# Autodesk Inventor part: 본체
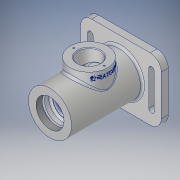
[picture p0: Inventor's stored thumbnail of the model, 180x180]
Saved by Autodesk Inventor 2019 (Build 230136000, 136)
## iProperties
Created: 2021-07
Part Number: 본체
Material: 알루미늄 6061
Document SubType Name: Modeling
Designer: jun-2-10
Mass: 738.051 g
Surface Area: 647.155 cm^2
Volume: 273.352 cm^3
Density: 2.7 g/cm^3
Appearance: 알루미늄 - 평지
Author: jun-2-10
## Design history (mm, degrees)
sketch "스케치1"
  geometry: C1 r 31 at (0, 0); 1 further point
  constraints: 1 centre point, 1 coincident
  dimensions: "d0" = 62 diameter of C1
extrude "돌출1" new body sketch "스케치1" stored distance "d1" = 115; taper "d2" = 0 deg
sketch "스케치2"
  geometry: C1 r 35 at (0, 0); 1 further point
  constraints: 1 centre point, 1 coincident
  dimensions: "d3" = 70 diameter of C1
extrude "돌출2" join sketch "스케치2" distance "d4" = 3; taper "d5" = 0 deg
sketch "스케치3"
  geometry: L1 (-58, 45)-(58, 45); L2 (58, 45)-(58, -45); L3 (58, -45)-(-58, -45); L4 (-58, -45)-(-58, 45); L5 (-58, 45)-(58, -45); L6 (58, 45)-(-58, -45); 1 further point
  constraints: 12 end point, 2 midpoint, 2 parallel, 1 horizontal, 1 perpendicular
  dimensions: "d6" = 116 distance of L1.start L1.end; "d7" = 90 distance of L1.end L2.end
extrude "돌출3" join sketch "스케치3" distance "d8" = 10; taper "d9" = 0 deg
sketch "스케치4"
  geometry: L1 (17.5, 31.5)-(17.5, 20.5); L2 (17.5, 20.5)-(23, 20.5); L3 (26, 17.5)-(26, -14.5); L4 (23, -17.5)-(17.5, -17.5); L5 (17.5, -17.5)-(17.5, -28.5); L6 (17.5, -28.5)-(16, -28.5); L7 (16, -28.5)-(16, -30.5); L8 (13, -33.5)-(10, -33.5); L9 (10, -33.5)-(10, -36.2); L10 (16.779, -45.318)-(22, -57.5); L11 (0, 80.5)-(0, -80.5) reference; L12 (31, -44.5)-(31, 57.5) reference; L13 (-31, -44.5)-(-31, 57.5) reference; L14 (35, -57.5)-(-35, -57.5) reference; L15 (14.022, -43.5)-(12.5, -43.5); L16 (12.5, -43.5)-(12.5, -36.5); L17 (12.2, -36.2)-(10, -36.2); L18 (17.5, 31.5)-(18.5, 31.5); L19 (18.5, 31.5)-(18.5, 33.25); L20 (18.5, 33.25)-(17.5, 33.25); L21 (17.5, 33.25)-(17.5, 36.5); L22 (17.5, 36.5)-(17, 36.5); L23 (20, 39.5)-(20, 45.5); L24 (20, 45.5)-(24, 45.5); L25 (24, 45.5)-(24, 48.5); L26 (24, 48.5)-(21, 48.5); L27 (31, 57.5)-(-31, 57.5) reference; L28 (22, -57.5)-(0, -57.5); L29 (21, 48.5)-(0, 48.5); L30 (0, 48.5)-(0, -57.5); A1 r 3 centre (17, 39.5) between (17, 36.5) and (20, 39.5); A2 r 3 centre (13, -30.5) between (13, -33.5) and (16, -30.5); A3 r 0.3 centre (12.2, -36.5) between (12.5, -36.5) and (12.2, -36.2); A4 r 3 centre (23, 17.5) between (26, 17.5) and (23, 20.5); A5 r 3 centre (23, -14.5) between (23, -17.5) and (26, -14.5); A6 r 3 centre (14.022, -46.5) between (16.779, -45.318) and (14.022, -43.5); 7 further points
  constraints: 50 end point, 20 perpendicular, 12 point on circle, 12 tangent, 10 point on line, 6 centre point, 2 horizontal, 1 equal radius, 1 midpoint
  dimensions: "d11" = 14 vertical distance of L10.end point (16, -43.5); "d12" = 44 diameter of L10.end L11; "d13" = 32 diameter of point (16, -43.5) L11; "d14" = 24 distance between parallel lines of L14 L8; "d15" = 20 diameter of L9 L11; "d16" = 52 diameter of L3 L11; "d17" = 35 diameter of L1 L11; "d18" = 11 distance of L4.end L5.end; "d20" = 7.3 distance of L15.end point (12.5, -36.2); "d21" = 25 diameter of L16 L11; "d22" = 32 diameter of L7 L11; "d23" = 35 diameter of L5 L11; "d24" = 38 distance of point (26, 20.5) point (26, -17.5); "d27" = 12 distance between parallel lines of L27 L24; "d29" = 1.75 distance of L18.end L19.end; "d30" = 37 diameter of L19 L11; "d31" = 35 diameter of L21 L11; "d32" = 21 distance between parallel lines of L27 L22; "d33" = 40 diameter of L23 L11; "d34" = 48 diameter of L25 L11; "d35" = 3 distance of L24.end L25.end; "d37" = 11 distance of L1.start L1.end; "d38" = 3 radius of A1; "d39" = 65 distance from line of L6 L21.end; "d40" = 3 radius of A2 (derived); "d41" = 0.3 radius of A3; "d42" = 3 radius of A4; "d43" = 3 radius of A6 (derived)
revolve "회전1" sketch "스케치4" stored, may be unused: angle "d44" = 90 deg
sketch "스케치7"
  geometry: 2 further points
  constraints: 1 coincident
hole "구멍1" sketch "스케치7" at (0, 0) diameter "d48" = 40.376; stored, may be unused: countersink angle "d52" = 90 deg, drill point angle "d54" = 0 deg; dims "d49" = 9, "d50" = 4, "d51" = 2, "d53" = 9
fillet "모깎기1" dims "d55" = 16
node "작업 평면1"
sketch "스케치9"
  geometry: L1 (0, -80.5)-(0, 80.5) reference; L2 (-81.2, 0)-(81.2, 0) reference; L3 (31, 57.5)-(-31, 57.5) reference; C1 r 27 at (0, 1.5); 1 further point
  constraints: 1 centre point, 1 point on line
  dimensions: "d58" = 54 diameter of C1; "d59" = 56 distance from line of L3 C1.centre
extrude "돌출4" join sketch "스케치9" stored distance "d60" = 10; taper "d61" = 0 deg
sketch "스케치10"
  geometry: C1 r 27 at (0, 0) reference; C2 r 16 at (0, 0); 1 further point
  constraints: 1 centre point, 1 coincident
  dimensions: "d62" = 32 diameter of C2
extrude "돌출5" cut sketch "스케치10" stored distance "d63" = 10; taper "d64" = 0 deg
sketch "스케치11"
  geometry: L1 (0, 82)-(0, -79) reference; L2 (22, 0)-(-22, 0); L3 (-31, -56)-(31, -56) reference; C1 r 16 at (0, 0) reference; C2 r 27 at (0, 0) reference; A1 r 22 centre (0, 0) between (22, 0) and (-22, 0); 3 further points
  constraints: 3 coincident, 2 end point, 2 point on circle, 1 centre point, 1 horizontal
  dimensions: "d65" = 44 diameter of A1; "d66" = 56 distance between parallel lines of L3 L2
hole "구멍2" sketch "스케치11" at (-22, 0), (22, 0) diameter "d67" = 2.459; stored, may be unused: countersink angle "d71" = 90 deg, drill point angle "d73" = 118 deg; dims "d68" = 6, "d69" = 4, "d70" = 2, "d72" = 8
sketch "스케치12"
  geometry: L1 (-81.2, 0)-(81.2, 0) reference; L2 (0, -63)-(0, 63) reference; L3 (-44, -25)-(-44, 25); L4 (-48, -25)-(-48, 25); L5 (-40, 25)-(-40, -25); L6 (44, -25)-(44, 25); L7 (40, -25)-(40, 25); L8 (48, 25)-(48, -25); A1 r 4 centre (-44, -25) between (-48, -25) and (-40, -25); A2 r 4 centre (-44, 25) between (-40, 25) and (-48, 25); A3 r 4 centre (44, -25) between (40, -25) and (48, -25); A4 r 4 centre (44, 25) between (48, 25) and (40, 25); 3 further points
  constraints: 16 end point, 8 point on circle, 8 tangent, 4 centre point, 2 midpoint, 2 parallel, 2 perpendicular, 2 point on line
  dimensions: "d74" = 4 radius of A4; "d75" = 50 distance of L6.start L6.end; "d76" = 50 distance of L3.start L3.end; "d77" = 44 distance between parallel lines of L6 L2; "d78" = 44 distance between parallel lines of L2 L3; "d79" = 4 radius of A2
extrude "돌출6" cut sketch "스케치12" extent not by distance; stored distance "d80" = 10; taper "d81" = 0 deg
fillet "모깎기2" dims "d82" = 3
chamfer "모따기2" distance "d83" = 1; stored, may be unused: second distance "d84" = 2, angle "d85" = 30 deg
node "작업 평면2"
sketch "스케치14"
  geometry: L1 (42, -15.5)-(42, 18.5) reference; L2 (42, 1.5)-(-31, 1.5); L3 (-31, -41.5)-(-31, 57.5) reference; 2 further points
  constraints: 2 end point, 2 point on line, 1 horizontal, 1 midpoint, 1 other
  dimensions: "d87" = 8 distance from line of L1 point (34, 1.5)
feature "엠보싱1" sketch "스케치14" dims "d88" = 0.5, "d89" = 0
chamfer "모따기3" distance "d90" = 1; stored, may be unused: second distance "d91" = 2, angle "d92" = 30 deg
fillet "모깎기3" dims "d93" = 0.3
chamfer "모따기4" distance "d94" = 0.7; stored, may be unused: second distance "d95" = 2, angle "d96" = 30 deg
node "솔리드1"
node "투영된 루프1"
node "투영된 루프2"
other parameters: "d56" = 42, "d86" = 67
